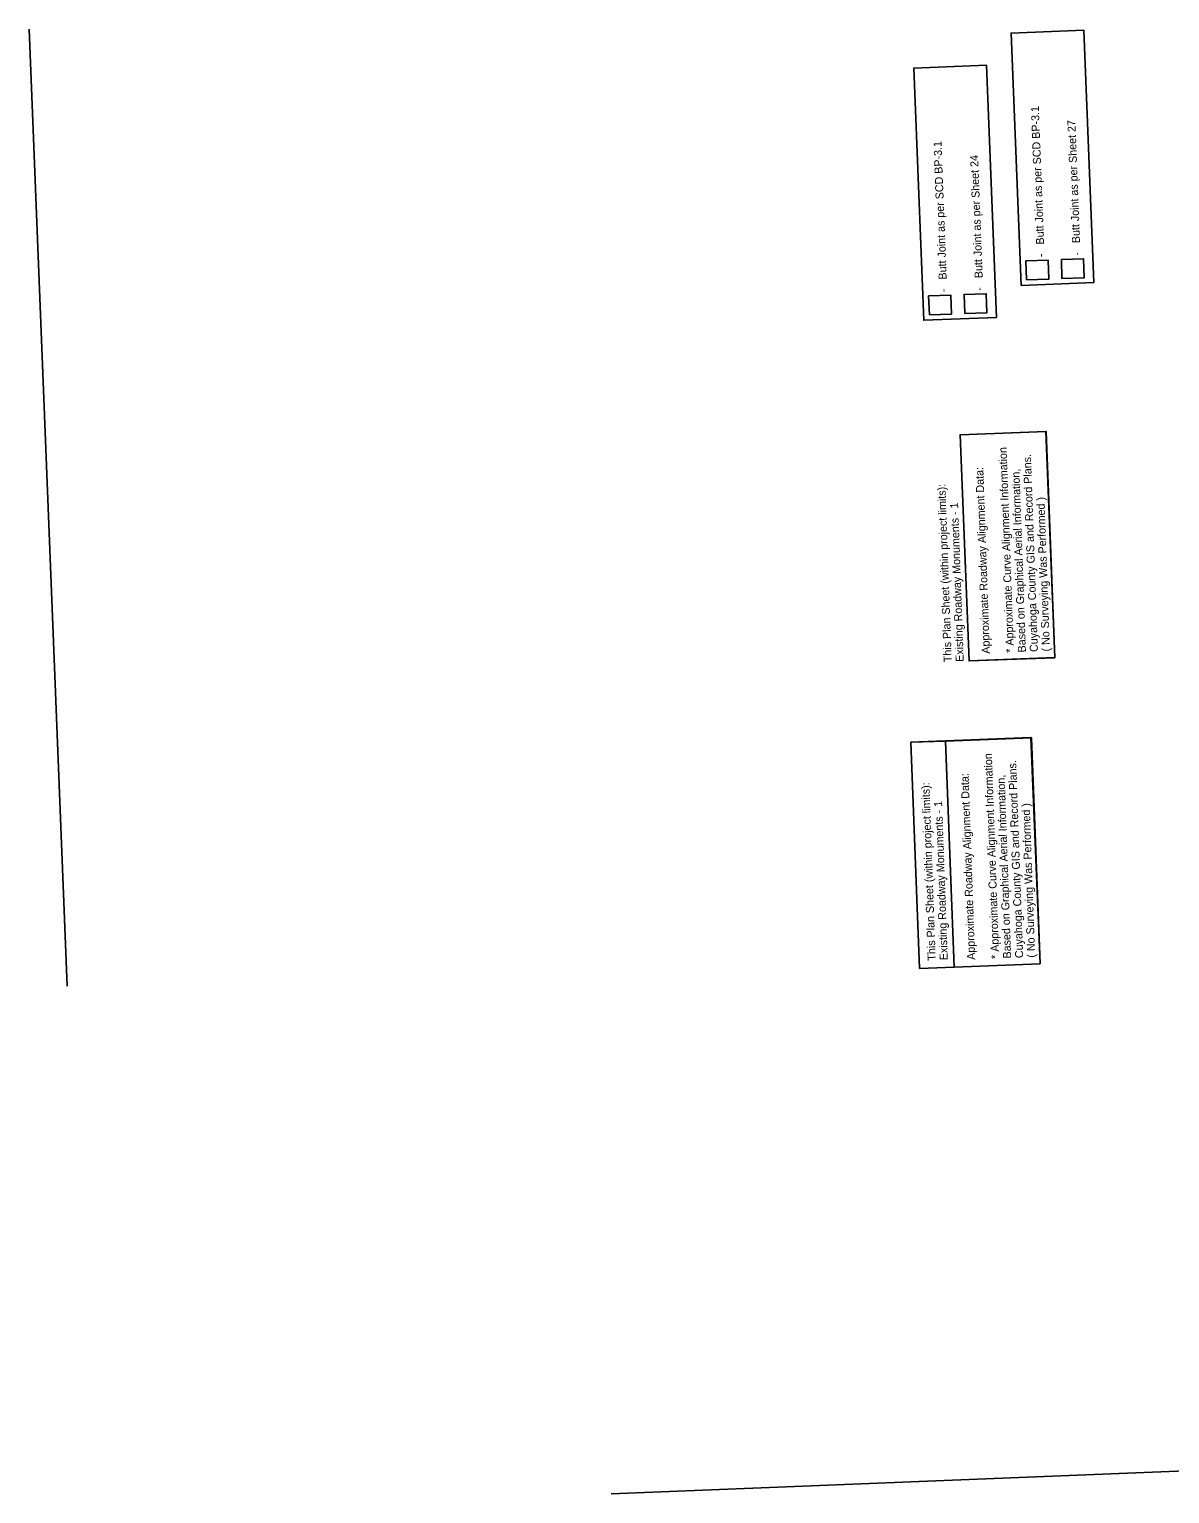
# Model space of a CAD drawing. Extents: x 2317581 to 2320275, y 612406 to 616674.
# Drawn here: x 2317581 to 2318579, y 614105 to 615386 of the extents above; entities that cross this region are included whole.
import ezdxf

# ---------------------------------------------------------------- set-up
doc = ezdxf.new("R2010")
doc.units = 0
for name, color, linetype in [('SC_Scratch1', 7, 'Continuous'), ('SC_Shading3', 7, 'Continuous'), ('SH_Data', 7, 'Continuous'), ('TX_P_50', 7, 'Continuous')]:
    doc.layers.add(name, color=color, linetype=linetype)

msp = doc.modelspace()

# ---------------------------------------------------------------- linework, layer by layer
at = {"layer": 'SC_Scratch1'}
for p, q in [((2317614.3, 614548.7), (2317581.2, 615385.8)), ((2318632.9, 614126.3), (2318090.1, 614104.8))]:
    msp.add_line(p, q, dxfattribs=at)
at = {"layer": 'SC_Shading3'}
for points in [[(2318427.2, 615133.7), (2318418.5, 615354.4), (2318354.8, 615351.9), (2318363.5, 615131.2)], [(2318478.1, 614836.2), (2318470.3, 615034), (2318395.3, 615031.1), (2318403.1, 614833.2)], [(2318390.2, 614565.5), (2318382.4, 614763.3), (2318352.2, 614762.1), (2318359.9, 614564.3)], [(2318465.2, 614568.4), (2318457.3, 614766.3), (2318382.4, 614763.3), (2318390.2, 614565.5)]]:
    msp.add_lwpolyline(points, close=True, dxfattribs=at)
at = {"layer": 'SH_Data'}
for points in [[(2318478.3, 614836.1), (2318470.6, 615033.9), (2318395.5, 615031), (2318403.1, 614833.2)], [(2318390.2, 614565.5), (2318382.6, 614763.2), (2318352.2, 614762.1), (2318359.9, 614564.3)], [(2318465.4, 614568.4), (2318457.7, 614766.1), (2318382.6, 614763.2), (2318390.2, 614565.5)]]:
    msp.add_lwpolyline(points, close=True, dxfattribs=at)
at = {"layer": 'TX_P_50'}
for points in [[(2318448.6, 615161.8), (2318439.9, 615382.5), (2318503.6, 615385), (2318512.3, 615164.3)], [(2318363.5, 615131.2), (2318354.8, 615351.9), (2318418.5, 615354.4), (2318427.2, 615133.7)], [(2318453.5, 615166.6), (2318472.9, 615167.2), (2318472.4, 615183.8), (2318452.9, 615183.2)], [(2318484.4, 615167.8), (2318503.9, 615168.5), (2318503.3, 615185), (2318483.9, 615184.4)], [(2318368.4, 615136), (2318387.8, 615136.6), (2318387.2, 615153.2), (2318367.8, 615152.5)], [(2318399.3, 615137.2), (2318418.8, 615137.8), (2318418.2, 615154.4), (2318398.8, 615153.8)]]:
    msp.add_lwpolyline(points, close=True, dxfattribs=at)

# ---------------------------------------------------------------- texts
at = {"layer": 'SH_Data'}
for s, p in [('* Approximate Curve Alignment Information', (2318442.4, 614840.5)), ('Cuyahoga County GIS and Record Plans.', (2318463.4, 614841.2)), ('Approximate Roadway Alignment Data:', (2318421.4, 614839.7)), ('Based on Graphical Aerial Information,', (2318452.9, 614840.8)), ('This Plan Sheet (within project limits):', (2318388, 614832.3)), ('( No Surveying Was Performed )', (2318473.9, 614841.6)), ('Existing Roadway Monuments - 1', (2318398.5, 614832.6)), ('* Approximate Curve Alignment Information', (2318429.5, 614572.7)), ('Cuyahoga County GIS and Record Plans.', (2318450.5, 614573.4)), ('Approximate Roadway Alignment Data:', (2318408.5, 614571.9)), ('Based on Graphical Aerial Information,', (2318440, 614573.1)), ('This Plan Sheet (within project limits):', (2318374, 614571.2)), ('Existing Roadway Monuments - 1', (2318384.5, 614571.6)), ('( No Surveying Was Performed )', (2318461, 614573.8))]:
    msp.add_text(s, height=7, rotation=92.0526, dxfattribs=at).set_placement(p)
at = {"layer": 'TX_P_50'}
for s, p in [('-   Butt Joint as per SCD BP-3.1', (2318469.2, 615186.7)), ('-   Butt Joint as per Sheet 27', (2318500.6, 615187.9)), ('-   Butt Joint as per SCD BP-3.1', (2318384, 615156.1)), ('-   Butt Joint as per Sheet 24', (2318415.5, 615157.3))]:
    msp.add_text(s, height=7, rotation=92.1748, dxfattribs=at).set_placement(p)

doc.saveas('drawing.dxf')
